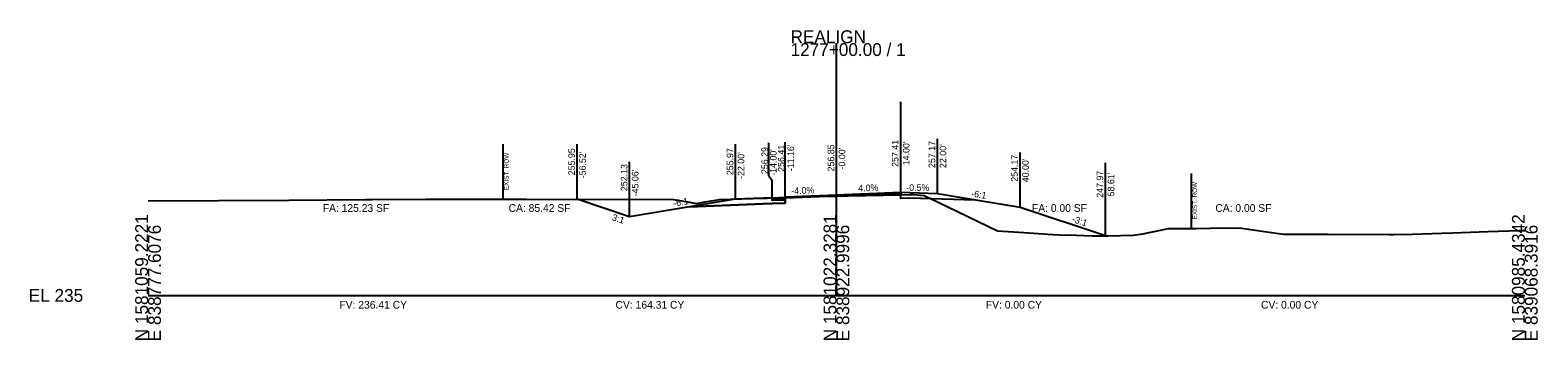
# Model space of a CAD drawing. Extents: x -26 to 6303, y -16 to 9563.
# Drawn here: x 5974.3 to 6302.8, y 990.3 to 1057.8 of the extents above; entities that cross this region are included whole.
import ezdxf

# ---------------------------------------------------------------- set-up
doc = ezdxf.new("R2010")
doc.units = 0
for name, color, linetype in [('ASPHALT_19MM1', 7, 'Continuous'), ('ASPHALT_9_5MM1', 7, 'Continuous'), ('Default', 7, 'Continuous'), ('Draft_XS_Grid', 7, 'Continuous'), ('DTM_TEMP_DROP', 7, 'Continuous'), ('DTM_X_GROUND', 7, 'Continuous'), ('X_TRANS_EOP', 7, 'Continuous'), ('XS_CELL', 7, 'Continuous'), ('XS_M_SHAPES_EARTHWORK', 7, 'Continuous'), ('XS_P_ASPHALT', 7, 'Continuous'), ('XS_P_GROUND', 7, 'Continuous'), ('XS_P_SHOULDER', 7, 'Continuous'), ('XS_P_SUBGRADE_GRANULAR', 7, 'Continuous'), ('XS_P_SUBGRADE_LEVELING', 7, 'Continuous'), ('XS_P_SUBGRADE_MILLING', 7, 'Continuous'), ('XS_P_TX_CLEARZONE', 7, 'Continuous'), ('XS_P_TX_FS_BS', 7, 'Continuous'), ('XS_SHEET_EW_TX_AREA', 7, 'Continuous'), ('XS_SHEET_EW_TX_VOLUME', 7, 'Continuous'), ('XS_X_ROW', 7, 'Continuous')]:
    doc.layers.add(name, color=color, linetype=linetype)

msp = doc.modelspace()

# ---------------------------------------------------------------- linework, layer by layer
at = {"layer": 'ASPHALT_19MM1'}
msp.add_lwpolyline([(6138.84, 1021.07), (6138.84, 1020.8), (6136, 1020.69), (6136, 1020.96), (6138.84, 1021.07)], dxfattribs=at)
at = {"layer": 'ASPHALT_9_5MM1'}
msp.add_lwpolyline([(6138.84, 1021.41), (6138.84, 1021.28), (6136, 1021.17), (6136, 1021.29), (6138.84, 1021.41)], dxfattribs=at)
at = {"layer": 'Default'}
msp.add_lwpolyline([(6138.84, 1021.28), (6138.84, 1021.07), (6136, 1020.96), (6136, 1021.17), (6138.84, 1021.28)], dxfattribs=at)
at = {"layer": 'DTM_X_GROUND'}
msp.add_lwpolyline([(6000, 1020.62), (6030.64, 1020.79), (6047.31, 1020.91), (6048.84, 1020.91), (6060.56, 1020.98), (6082.44, 1020.96), (6114.51, 1020.91), (6117.15, 1020.47), (6119.54, 1020.05), (6121.42, 1020.38), (6124.55, 1020.89), (6131.78, 1021.12), (6134.9, 1021.21), (6138.01, 1021.36), (6138.84, 1021.4), (6145.53, 1021.55), (6152.58, 1021.71), (6165.9, 1021.99), (6166.67, 1022), (6166.78, 1021.99), (6169.15, 1021.77), (6172.17, 1020.35), (6185.13, 1014.1), (6189.78, 1013.8), (6197.13, 1013.31), (6198.61, 1013.21), (6202.33, 1013.12), (6205.71, 1013.02), (6209.13, 1012.96), (6214.64, 1013.16), (6216.76, 1013.44), (6222.38, 1014.62), (6228.36, 1014.61), (6231.41, 1014.65), (6237.74, 1014.72), (6245.81, 1013.6), (6247.52, 1013.39), (6248.03, 1013.38), (6256.64, 1013.33), (6257.17, 1013.33), (6270.37, 1013.3), (6271.43, 1013.3), (6275.53, 1013.32), (6281.84, 1013.58), (6284.32, 1013.66), (6291.97, 1013.95), (6298.79, 1014.13), (6300, 1014.17)], dxfattribs=at)
at = {"layer": 'X_TRANS_EOP'}
msp.add_line((6164, 1022.21), (6164, 1042.21), dxfattribs=at)
at = {"layer": 'XS_CELL'}
for p, q in [((6150, 1000), (6150, 1055)), ((6000, 1000), (6150, 1000)), ((6150, 1000), (6300, 1000))]:
    msp.add_line(p, q, dxfattribs=at)
at = {"layer": 'XS_M_SHAPES_EARTHWORK'}
for points in [[(6164, 1021.95), (6165.9, 1021.99), (6166.67, 1022), (6166.78, 1021.99), (6169.15, 1021.77), (6170.62, 1021.08), (6166, 1021.22), (6164, 1021.14)], [(6093.48, 1020.95), (6114.51, 1020.91), (6117.15, 1020.47), (6119.54, 1020.05), (6121.42, 1020.38), (6124.55, 1020.89), (6131.78, 1021.12), (6134.9, 1021.21), (6138.01, 1021.36), (6138.84, 1021.4), (6145.53, 1021.55), (6145.77, 1021.56), (6145.53, 1021.55), (6138.84, 1021.28), (6138.84, 1021.07), (6138.84, 1020.8), (6138.84, 1020.13), (6136, 1020.02), (6134, 1019.94), (6117.97, 1019.3), (6104.94, 1017.13)], [(6170.62, 1021.08), (6172.17, 1020.35), (6185.13, 1014.1), (6189.78, 1013.8), (6197.13, 1013.31), (6198.61, 1013.21), (6202.33, 1013.12), (6205.71, 1013.02), (6208.61, 1012.97), (6190, 1019.17), (6180.27, 1020.79)]]:
    msp.add_lwpolyline(points, close=True, dxfattribs=at)
at = {"layer": 'XS_P_ASPHALT'}
msp.add_lwpolyline([(6138.84, 1021.28), (6138.84, 1021.28), (6150, 1021.73), (6150, 1021.73), (6164, 1022.29), (6164, 1022.41), (6150, 1021.85), (6150, 1021.85), (6138.84, 1021.41), (6138.84, 1021.41), (6138.84, 1021.28)], dxfattribs=at)
at = {"layer": 'XS_P_GROUND'}
for points in [[(6208.61, 1012.97), (6190, 1019.17), (6190, 1019.17), (6190, 1019.17), (6172, 1022.17)], [(6128, 1020.97), (6104.94, 1017.13), (6093.48, 1020.95)]]:
    msp.add_lwpolyline(points, dxfattribs=at)
at = {"layer": 'XS_P_SHOULDER'}
for points in [[(6172, 1022.17), (6172, 1022.17), (6164, 1022.41)], [(6136, 1021.29), (6128, 1020.97)]]:
    msp.add_lwpolyline(points, dxfattribs=at)
at = {"layer": 'XS_P_SUBGRADE_GRANULAR'}
for points in [[(6164, 1021.14), (6164, 1022.41)], [(6117.97, 1019.3), (6117.97, 1019.3), (6134, 1019.94), (6134, 1019.94), (6136, 1020.02)], [(6136, 1020.02), (6136, 1020.02), (6138.84, 1020.13)], [(6138.84, 1020.13), (6138.84, 1021.41)], [(6180.27, 1020.79), (6180.27, 1020.79), (6166, 1021.22), (6164, 1021.14), (6164, 1021.14)]]:
    msp.add_lwpolyline(points, dxfattribs=at)
at = {"layer": 'XS_P_SUBGRADE_LEVELING'}
msp.add_lwpolyline([(6138.84, 1021.28), (6145.53, 1021.55), (6145.53, 1021.55), (6150, 1021.73), (6150, 1021.73), (6152.58, 1021.83), (6152.58, 1021.83), (6164, 1022.29), (6164, 1022.29), (6164, 1021.95), (6164, 1021.95), (6164, 1021.95), (6152.58, 1021.71), (6152.58, 1021.71), (6150, 1021.65), (6150, 1021.65), (6150, 1021.65), (6145.77, 1021.56), (6145.53, 1021.55), (6145.53, 1021.55), (6138.84, 1021.28)], dxfattribs=at)
at = {"layer": 'XS_P_SUBGRADE_MILLING'}
msp.add_lwpolyline([(6164, 1021.95), (6164, 1021.95), (6152.58, 1021.71), (6152.58, 1021.71), (6150, 1021.65), (6150, 1021.65), (6150, 1021.65), (6145.77, 1021.56), (6145.53, 1021.55), (6145.53, 1021.55), (6138.84, 1021.28), (6138.84, 1021.28), (6138.84, 1021.4), (6145.53, 1021.55), (6145.53, 1021.55), (6150, 1021.65), (6150, 1021.65), (6152.58, 1021.71), (6152.58, 1021.71), (6164, 1021.95), (6164, 1021.95)], dxfattribs=at)
at = {"layer": 'XS_P_TX_CLEARZONE'}
for p, q in [((6093.48, 1020.95), (6093.48, 1032.95)), ((6128, 1020.97), (6128, 1032.97)), ((6135.3, 1026.04), (6135.3, 1033.29)), ((6138.84, 1021.41), (6138.84, 1033.41)), ((6150, 1021.85), (6150, 1033.85)), ((6164, 1022.41), (6164, 1034.41)), ((6172, 1022.17), (6172, 1034.17)), ((6104.94, 1017.13), (6104.94, 1029.13)), ((6190, 1019.17), (6190, 1031.17)), ((6208.61, 1012.97), (6208.61, 1028.9)), ((6135.3, 1026.04), (6136, 1025.06)), ((6136, 1021.29), (6136, 1025.06))]:
    msp.add_line(p, q, dxfattribs=at)
at = {"layer": 'XS_X_ROW'}
for p, q in [((6077.36, 1020.97), (6077.36, 1032.97)), ((6227.38, 1014.61), (6227.38, 1026.61))]:
    msp.add_line(p, q, dxfattribs=at)

# ---------------------------------------------------------------- texts
at = {"layer": 'Draft_XS_Grid'}
msp.add_text('-', height=0.0001, dxfattribs=at).set_placement((6000, 1000))
at = {"layer": 'DTM_TEMP_DROP'}
for p in [(6149.92, 1021.73), (6163.92, 1022.29), (6135.92, 1021.17), (6138.77, 1021.29)]:
    msp.add_text('X', height=0.24, dxfattribs=at).set_placement(p)
at = {"layer": 'X_TRANS_EOP'}
for p in [(6093.4, 1020.83), (6208.53, 1012.85)]:
    msp.add_text('X', height=0.24, dxfattribs=at).set_placement(p)
at = {"layer": 'XS_CELL'}
for s, p in [('1277+00.00 / 1', (6140, 1052.2)), ('REALIGN', (6140, 1055)), ('EL 235', (5974, 998.6))]:
    msp.add_text(s, height=2.8, dxfattribs=at).set_placement(p)
for s, p in [('N 1581059.2221', (6000, 990)), ('E 838777.6076', (6002.8, 990)), ('N 1581022.3281', (6150, 990)), ('E 838922.9996', (6152.8, 990)), ('N 1580985.4342', (6300, 990)), ('E 839068.3916', (6302.8, 990))]:
    msp.add_text(s, height=2.8, rotation=90, dxfattribs=at).set_placement(p)
at = {"layer": 'XS_P_ASPHALT'}
msp.add_text('X', height=0.24, dxfattribs=at).set_placement((6189.92, 1019.05))
at = {"layer": 'XS_P_SHOULDER'}
for p in [(6171.92, 1022.05), (6127.92, 1020.85)]:
    msp.add_text('X', height=0.24, dxfattribs=at).set_placement(p)
at = {"layer": 'XS_P_SUBGRADE_GRANULAR'}
for p in [(6104.86, 1017.01), (6208.53, 1012.85)]:
    msp.add_text('X', height=0.24, dxfattribs=at).set_placement(p)
at = {"layer": 'XS_P_TX_CLEARZONE'}
for s, p in [('255.95', (6093, 1026.19)), ('255.97', (6127.52, 1026.22)), ('256.29', (6135.09, 1026.46)), ("-14.00'", (6136.95, 1026.08)), ('256.41', (6138.68, 1026.95)), ("-11.16'", (6140.76, 1027.08)), ('256.85', (6149.52, 1027.03)), ("-0.00'", (6151.92, 1027.46)), ('257.41', (6163.52, 1028.02)), ("14.00'", (6165.92, 1028.38)), ('257.17', (6171.52, 1027.78)), ("22.00'", (6173.92, 1027.78)), ("-56.52'", (6095.4, 1025.53)), ('252.13', (6104.46, 1022.74)), ("-22.00'", (6129.92, 1025.4)), ('254.17', (6189.52, 1024.78)), ("40.00'", (6191.92, 1024.67)), ("-45.06'", (6106.86, 1021.6)), ('247.97', (6208.13, 1021.29)), ("58.61'", (6210.53, 1021.59))]:
    msp.add_text(s, height=1.44, rotation=90, dxfattribs=at).set_placement(p)
at = {"layer": 'XS_P_TX_FS_BS'}
for s, rotation, p in [('-4.0%', 2.2906, (6140.18, 1022.06)), ('4.0%', 2.2906, (6154.77, 1022.64)), ('-0.5%', 359.7263, (6165.21, 1022.8)), ('-6:1', 350.5377, (6179.28, 1021.57)), ('-6:1', 9.4642, (6114.55, 1019.34)), ('3:1', 341.5668, (6100.97, 1016.44)), ('-3:1', 341.5651, (6201.22, 1016.05))]:
    msp.add_text(s, height=1.44, rotation=rotation, dxfattribs=at).set_placement(p)
at = {"layer": 'XS_SHEET_EW_TX_AREA'}
for s, p in [('FA: 125.23 SF', (6038.07, 1018.22)), ('CA: 85.42 SF', (6078.57, 1018.22)), ('FA: 0.00 SF', (6192.6, 1018.22)), ('CA: 0.00 SF', (6232.56, 1018.22))]:
    msp.add_text(s, height=1.68, dxfattribs=at).set_placement(p)
at = {"layer": 'XS_SHEET_EW_TX_VOLUME'}
for s, p in [('FV: 236.41 CY', (6041.69, 997.12)), ('CV: 164.31 CY', (6101.87, 997.12)), ('FV: 0.00 CY', (6182.55, 997.12)), ('CV: 0.00 CY', (6242.51, 997.12))]:
    msp.add_text(s, height=1.68, dxfattribs=at).set_placement(p)
at = {"layer": 'XS_X_ROW'}
for p in [(6078.56, 1022.97), (6228.58, 1016.61)]:
    msp.add_text('EXIST. ROW', height=1, rotation=90, dxfattribs=at).set_placement(p)

doc.saveas('drawing.dxf')
